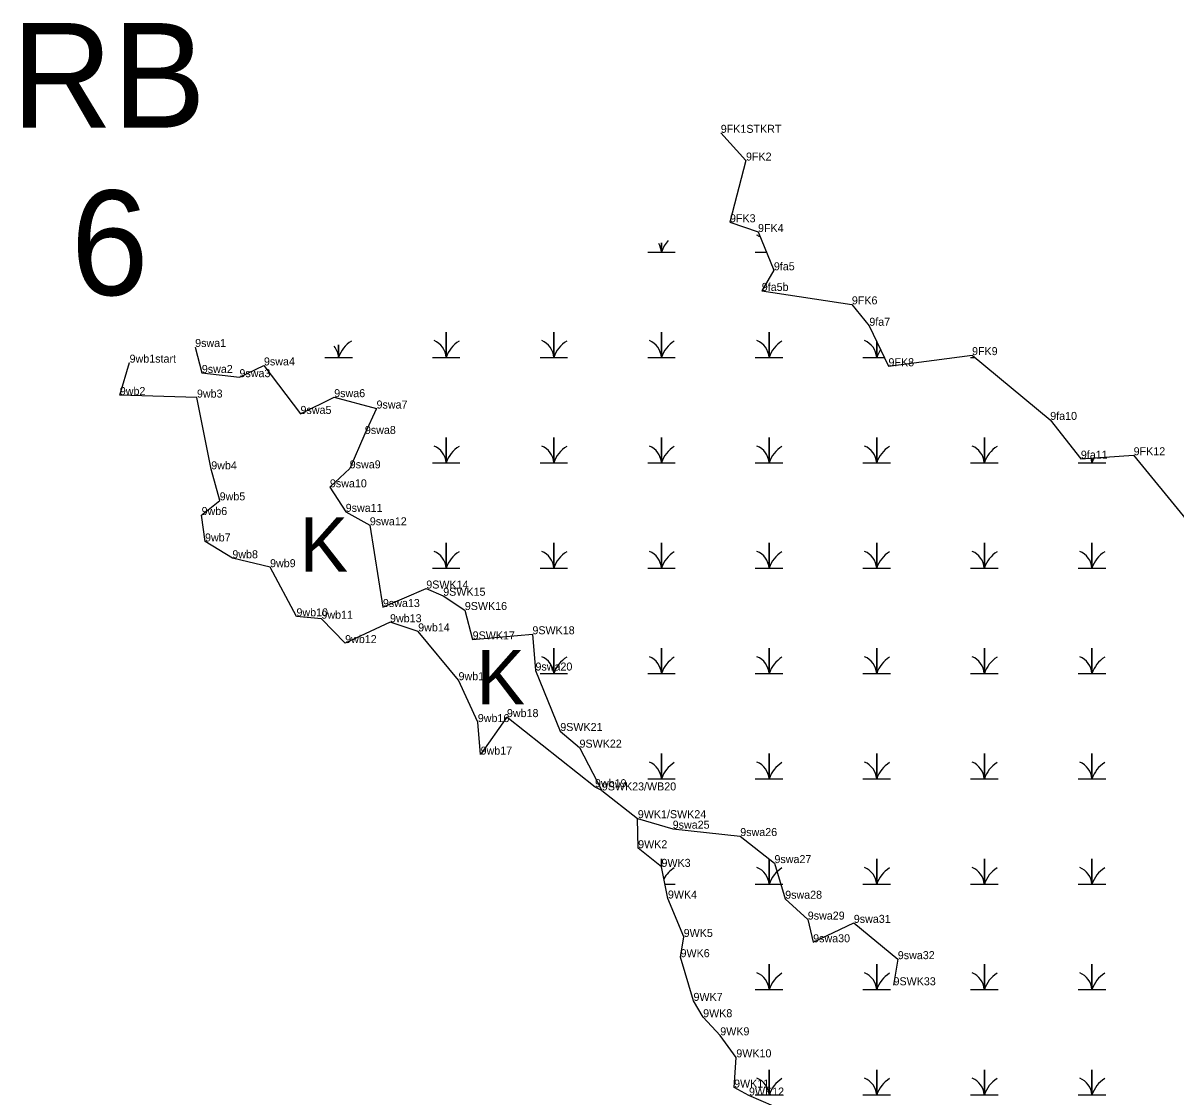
# Model space of a CAD drawing. Extents: x 2072529 to 2268796, y 436423 to 470406.
# Drawn here: x 2211830 to 2212551, y 449541 to 450212 of the extents above; entities that cross this region are included whole.
import ezdxf

# ---------------------------------------------------------------- set-up
doc = ezdxf.new("R2010")
doc.units = 0
for name, color, linetype in [('Default', 7, 'Continuous'), ('Exist Environmental Wetland Boundary', 7, 'Continuous'), ('Exist Environmental Wetland Boundary Cogo Comment', 7, 'Continuous'), ('Exist Hydro Jurisdictional Stream or Body of Water NEU Mitigable', 7, 'Continuous'), ('Exist Hydro Jurisdictional Stream or Body of Water NEU Mitigable Cogo Comment', 7, 'Continuous'), ('Exist Hydro Swamp or Marsh', 7, 'Continuous'), ('Old_Level_20', 7, 'Continuous')]:
    doc.layers.add(name, color=color, linetype=linetype)

msp = doc.modelspace()

# ---------------------------------------------------------------- linework, layer by layer
at = {"layer": 'Exist Environmental Wetland Boundary'}
for points in [[(2212266.45, 450143.23), (2212282.21, 450125.91), (2212272.2, 450087.37), (2212289.74, 450081.3), (2212299.63, 450057.38), (2212292.08, 450044.5), (2212348.37, 450036.11), (2212359.27, 450022.73), (2212371.25, 449997.47), (2212423.46, 450004.4), (2212472.32, 449963.94), (2212491.46, 449939.73), (2212524.45, 449941.86), (2212557.2, 449901.85)], [(2212192.12, 449732.56), (2212187.87, 449734.56), (2212132.83, 449778.34), (2212116.4, 449754.91), (2212114.63, 449775.24), (2212102.59, 449801.39), (2212077.37, 449831.86), (2212059.78, 449837.58), (2212031.73, 449824.56), (2212016.91, 449839.79), (2212001.31, 449841.26), (2211984.83, 449871.96), (2211961.26, 449877.54), (2211944.17, 449888.04), (2211942.04, 449904.54), (2211953.34, 449913.7), (2211948.07, 449933.08), (2211939.14, 449977.89), (2211890.93, 449979.47), (2211897.05, 449999.7)], [(2212299.43, 449535.26), (2212284.07, 449542), (2212274.77, 449546.95), (2212276.16, 449565.86), (2212266.13, 449579.6), (2212255.44, 449590.92), (2212249.41, 449601.12), (2212241.33, 449628.41), (2212243.27, 449641.04), (2212233.43, 449665.04), (2212229.4, 449684.82), (2212214.82, 449696.44), (2212214.5, 449715.1)]]:
    msp.add_lwpolyline(points, dxfattribs=at)
at = {"layer": 'Exist Hydro Jurisdictional Stream or Body of Water NEU Mitigable'}
msp.add_lwpolyline([(2211938, 450009.47), (2211942.18, 449993.25), (2211965.69, 449990.64), (2211981, 449997.97), (2212003.85, 449967.68), (2212024.9, 449978.15), (2212051.36, 449971.04), (2212044.07, 449955.16), (2212034.6, 449933.69), (2212022.23, 449921.84), (2212032.07, 449906.53), (2212047.16, 449898.13), (2212055.34, 449847.07), (2212082.43, 449858.63), (2212093.02, 449854.12), (2212106.52, 449845.21), (2212111.4, 449826.87), (2212148.76, 449830.07), (2212150.66, 449807.4), (2212166.16, 449769.66), (2212178.19, 449759.28), (2212192.12, 449732.56), (2212214.5, 449715.1), (2212236.4, 449708.65), (2212278.62, 449704.05), (2212299.99, 449687.16), (2212306.69, 449664.9), (2212320.81, 449651.88), (2212324.18, 449637.71), (2212349.58, 449649.84), (2212377.06, 449627.18), (2212374.41, 449610.86)], dxfattribs=at)
at = {"layer": 'Exist Hydro Swamp or Marsh'}
for points in [[(2212220.78, 450068.77), (2212229.39, 450068.77), (2212229.39, 450074.57)], [(2212229.39, 450074.57), (2212229.39, 450068.77), (2212237.99, 450068.77)], [(2212288.03, 450068.77), (2212294.92, 450068.77)], [(2212086.28, 450002.97), (2212094.89, 450002.97), (2212094.89, 450018.75), (2212094.89, 450002.97), (2212103.49, 450002.97)], [(2212153.53, 450002.97), (2212162.14, 450002.97), (2212162.14, 450018.75), (2212162.14, 450002.97), (2212170.74, 450002.97)], [(2212220.78, 450002.97), (2212229.39, 450002.97), (2212229.39, 450018.75), (2212229.39, 450002.97), (2212237.99, 450002.97)], [(2212288.03, 450002.97), (2212296.64, 450002.97), (2212296.64, 450018.75), (2212296.64, 450002.97), (2212305.24, 450002.97)], [(2212355.28, 450002.97), (2212363.89, 450002.97), (2212363.89, 450013)], [(2212363.89, 450013), (2212363.89, 450002.97), (2212368.64, 450002.97)], [(2212019.03, 450002.97), (2212027.64, 450002.97), (2212027.64, 450010.77)], [(2212027.64, 450010.77), (2212027.64, 450002.97), (2212036.24, 450002.97)], [(2212422.53, 450002.97), (2212425.18, 450002.97)], [(2212086.28, 449937.17), (2212094.89, 449937.17), (2212094.89, 449952.95), (2212094.89, 449937.17), (2212103.49, 449937.17)], [(2212153.53, 449937.17), (2212162.14, 449937.17), (2212162.14, 449952.95), (2212162.14, 449937.17), (2212170.74, 449937.17)], [(2212220.78, 449937.17), (2212229.39, 449937.17), (2212229.39, 449952.95), (2212229.39, 449937.17), (2212237.99, 449937.17)], [(2212288.03, 449937.17), (2212296.64, 449937.17), (2212296.64, 449952.95), (2212296.64, 449937.17), (2212305.24, 449937.17)], [(2212355.28, 449937.17), (2212363.89, 449937.17), (2212363.89, 449952.95), (2212363.89, 449937.17), (2212372.49, 449937.17)], [(2212422.53, 449937.17), (2212431.14, 449937.17), (2212431.14, 449952.95), (2212431.14, 449937.17), (2212439.74, 449937.17)], [(2212489.78, 449937.17), (2212498.39, 449937.17), (2212498.39, 449940.18)], [(2212498.39, 449940.18), (2212498.39, 449937.17), (2212506.99, 449937.17)], [(2212036.13, 449937.17), (2212036.24, 449937.17)], [(2212086.28, 449871.37), (2212094.89, 449871.37), (2212094.89, 449887.15), (2212094.89, 449871.37), (2212103.49, 449871.37)], [(2212153.53, 449871.37), (2212162.14, 449871.37), (2212162.14, 449887.15), (2212162.14, 449871.37), (2212170.74, 449871.37)], [(2212220.78, 449871.37), (2212229.39, 449871.37), (2212229.39, 449887.15), (2212229.39, 449871.37), (2212237.99, 449871.37)], [(2212288.03, 449871.37), (2212296.64, 449871.37), (2212296.64, 449887.15), (2212296.64, 449871.37), (2212305.24, 449871.37)], [(2212355.28, 449871.37), (2212363.89, 449871.37), (2212363.89, 449887.15), (2212363.89, 449871.37), (2212372.49, 449871.37)], [(2212422.53, 449871.37), (2212431.14, 449871.37), (2212431.14, 449887.15), (2212431.14, 449871.37), (2212439.74, 449871.37)], [(2212489.78, 449871.37), (2212498.39, 449871.37), (2212498.39, 449887.15), (2212498.39, 449871.37), (2212506.99, 449871.37)], [(2212153.53, 449805.57), (2212162.14, 449805.57), (2212162.14, 449821.35), (2212162.14, 449805.57), (2212170.74, 449805.57)], [(2212220.78, 449805.57), (2212229.39, 449805.57), (2212229.39, 449821.35), (2212229.39, 449805.57), (2212237.99, 449805.57)], [(2212288.03, 449805.57), (2212296.64, 449805.57), (2212296.64, 449821.35), (2212296.64, 449805.57), (2212305.24, 449805.57)], [(2212355.28, 449805.57), (2212363.89, 449805.57), (2212363.89, 449821.35), (2212363.89, 449805.57), (2212372.49, 449805.57)], [(2212422.53, 449805.57), (2212431.14, 449805.57), (2212431.14, 449821.35), (2212431.14, 449805.57), (2212439.74, 449805.57)], [(2212489.78, 449805.57), (2212498.39, 449805.57), (2212498.39, 449821.35), (2212498.39, 449805.57), (2212506.99, 449805.57)], [(2212220.78, 449739.77), (2212229.39, 449739.77), (2212229.39, 449755.55), (2212229.39, 449739.77), (2212237.99, 449739.77)], [(2212288.03, 449739.77), (2212296.64, 449739.77), (2212296.64, 449755.55), (2212296.64, 449739.77), (2212305.24, 449739.77)], [(2212355.28, 449739.77), (2212363.89, 449739.77), (2212363.89, 449755.55), (2212363.89, 449739.77), (2212372.49, 449739.77)], [(2212422.53, 449739.77), (2212431.14, 449739.77), (2212431.14, 449755.55), (2212431.14, 449739.77), (2212439.74, 449739.77)], [(2212489.78, 449739.77), (2212498.39, 449739.77), (2212498.39, 449755.55), (2212498.39, 449739.77), (2212506.99, 449739.77)], [(2212229.39, 449684.83), (2212229.39, 449689.75), (2212229.39, 449684.83)], [(2212288.03, 449673.97), (2212296.64, 449673.97), (2212296.64, 449689.75), (2212296.64, 449673.97), (2212305.24, 449673.97)], [(2212355.28, 449673.97), (2212363.89, 449673.97), (2212363.89, 449689.75), (2212363.89, 449673.97), (2212372.49, 449673.97)], [(2212422.53, 449673.97), (2212431.14, 449673.97), (2212431.14, 449689.75), (2212431.14, 449673.97), (2212439.74, 449673.97)], [(2212489.78, 449673.97), (2212498.39, 449673.97), (2212498.39, 449689.75), (2212498.39, 449673.97), (2212506.99, 449673.97)], [(2212231.61, 449673.97), (2212237.99, 449673.97)], [(2212288.03, 449608.17), (2212296.64, 449608.17), (2212296.64, 449623.95), (2212296.64, 449608.17), (2212305.24, 449608.17)], [(2212355.28, 449608.17), (2212363.89, 449608.17), (2212363.89, 449623.95), (2212363.89, 449608.17), (2212372.49, 449608.17)], [(2212422.53, 449608.17), (2212431.14, 449608.17), (2212431.14, 449623.95), (2212431.14, 449608.17), (2212439.74, 449608.17)], [(2212489.78, 449608.17), (2212498.39, 449608.17), (2212498.39, 449623.95), (2212498.39, 449608.17), (2212506.99, 449608.17)], [(2212288.03, 449542.37), (2212296.64, 449542.37), (2212296.64, 449558.15), (2212296.64, 449542.37), (2212305.24, 449542.37)], [(2212355.28, 449542.37), (2212363.89, 449542.37), (2212363.89, 449558.15), (2212363.89, 449542.37), (2212372.49, 449542.37)], [(2212422.53, 449542.37), (2212431.14, 449542.37), (2212431.14, 449558.15), (2212431.14, 449542.37), (2212439.74, 449542.37)], [(2212489.78, 449542.37), (2212498.39, 449542.37), (2212498.39, 449558.15), (2212498.39, 449542.37), (2212506.99, 449542.37)]]:
    msp.add_lwpolyline(points, dxfattribs=at)
for centre, radius, start, end in [((2212284.37, 450067.88), 12.3, 57.34248, 67.53497), ((2212217.12, 450067.88), 12.3, 4.14034, 30.12475), ((2212247.63, 450062.71), 19.22, 136.57429, 161.62219), ((2212045.88, 449996.91), 19.22, 122.12745, 161.62219), ((2212082.62, 450002.08), 12.3, 4.14034, 67.53497), ((2212113.13, 449996.91), 19.22, 122.12745, 161.62219), ((2212149.87, 450002.08), 12.3, 4.14034, 67.53497), ((2212180.38, 449996.91), 19.22, 122.12745, 161.62219), ((2212217.12, 450002.08), 12.3, 4.14034, 67.53497), ((2212247.63, 449996.91), 19.22, 122.12745, 161.62219), ((2212284.37, 450002.08), 12.3, 4.14034, 67.53497), ((2212314.88, 449996.91), 19.22, 122.12745, 161.62219), ((2212351.62, 450002.08), 12.3, 4.14034, 67.53497), ((2212015.37, 450002.08), 12.3, 4.14034, 39.4646), ((2212382.13, 449996.91), 19.22, 145.28894, 161.62219), ((2212082.62, 449936.28), 12.3, 4.14034, 67.53497), ((2212113.13, 449931.11), 19.22, 122.12745, 161.62219), ((2212149.87, 449936.28), 12.3, 4.14034, 67.53497), ((2212180.38, 449931.11), 19.22, 122.12745, 161.62219), ((2212217.12, 449936.28), 12.3, 4.14034, 67.53497), ((2212247.63, 449931.11), 19.22, 122.12745, 161.62219), ((2212284.37, 449936.28), 12.3, 4.14034, 67.53497), ((2212314.88, 449931.11), 19.22, 122.12745, 161.62219), ((2212351.62, 449936.28), 12.3, 4.14034, 67.53497), ((2212382.13, 449931.11), 19.22, 122.12745, 161.62219), ((2212418.87, 449936.28), 12.3, 4.14034, 67.53497), ((2212449.38, 449931.11), 19.22, 122.12745, 161.62219), ((2212486.12, 449936.28), 12.3, 4.14034, 18.30304), ((2212516.63, 449931.11), 19.22, 151.54291, 161.62219), ((2212082.62, 449870.48), 12.3, 4.14034, 67.53497), ((2212113.13, 449865.31), 19.22, 122.12745, 161.62219), ((2212149.87, 449870.48), 12.3, 4.14034, 67.53497), ((2212180.38, 449865.31), 19.22, 122.12745, 161.62219), ((2212217.12, 449870.48), 12.3, 4.14034, 67.53497), ((2212247.63, 449865.31), 19.22, 122.12745, 161.62219), ((2212284.37, 449870.48), 12.3, 4.14034, 67.53497), ((2212314.88, 449865.31), 19.22, 122.12745, 161.62219), ((2212351.62, 449870.48), 12.3, 4.14034, 67.53497), ((2212382.13, 449865.31), 19.22, 122.12745, 161.62219), ((2212418.87, 449870.48), 12.3, 4.14034, 67.53497), ((2212449.38, 449865.31), 19.22, 122.12745, 161.62219), ((2212486.12, 449870.48), 12.3, 4.14034, 67.53497), ((2212516.63, 449865.31), 19.22, 122.12745, 161.62219), ((2212149.87, 449804.68), 12.3, 4.14034, 67.53497), ((2212180.38, 449799.51), 19.22, 122.12745, 161.62219), ((2212217.12, 449804.68), 12.3, 4.14034, 67.53497), ((2212247.63, 449799.51), 19.22, 122.12745, 161.62219), ((2212284.37, 449804.68), 12.3, 4.14034, 67.53497), ((2212314.88, 449799.51), 19.22, 122.12745, 161.62219), ((2212351.62, 449804.68), 12.3, 4.14034, 67.53497), ((2212382.13, 449799.51), 19.22, 122.12745, 161.62219), ((2212418.87, 449804.68), 12.3, 4.14034, 67.53497), ((2212449.38, 449799.51), 19.22, 122.12745, 161.62219), ((2212486.12, 449804.68), 12.3, 4.14034, 67.53497), ((2212516.63, 449799.51), 19.22, 122.12745, 161.62219), ((2212217.12, 449738.88), 12.3, 4.14034, 67.53497), ((2212247.63, 449733.71), 19.22, 122.12745, 161.62219), ((2212284.37, 449738.88), 12.3, 4.14034, 67.53497), ((2212314.88, 449733.71), 19.22, 122.12745, 161.62219), ((2212351.62, 449738.88), 12.3, 4.14034, 67.53497), ((2212382.13, 449733.71), 19.22, 122.12745, 161.62219), ((2212418.87, 449738.88), 12.3, 4.14034, 67.53497), ((2212449.38, 449733.71), 19.22, 122.12745, 161.62219), ((2212486.12, 449738.88), 12.3, 4.14034, 67.53497), ((2212516.63, 449733.71), 19.22, 122.12745, 161.62219), ((2212247.63, 449667.91), 19.22, 122.12745, 150.42062), ((2212284.37, 449673.08), 12.3, 4.14034, 67.53497), ((2212314.88, 449667.91), 19.22, 122.12745, 161.62219), ((2212351.62, 449673.08), 12.3, 4.14034, 67.53497), ((2212382.13, 449667.91), 19.22, 122.12745, 161.62219), ((2212418.87, 449673.08), 12.3, 4.14034, 67.53497), ((2212449.38, 449667.91), 19.22, 122.12745, 161.62219), ((2212486.12, 449673.08), 12.3, 4.14034, 67.53497), ((2212516.63, 449667.91), 19.22, 122.12745, 161.62219), ((2212284.37, 449607.28), 12.3, 4.14034, 67.53497), ((2212314.88, 449602.11), 19.22, 122.12745, 161.62219), ((2212351.62, 449607.28), 12.3, 4.14034, 67.53497), ((2212382.13, 449602.11), 19.22, 122.12745, 161.62219), ((2212418.87, 449607.28), 12.3, 4.14034, 67.53497), ((2212449.38, 449602.11), 19.22, 122.12745, 161.62219), ((2212486.12, 449607.28), 12.3, 4.14034, 67.53497), ((2212516.63, 449602.11), 19.22, 122.12745, 161.62219), ((2212284.37, 449541.48), 12.3, 4.14034, 67.53497), ((2212314.88, 449536.31), 19.22, 122.12745, 161.62219), ((2212351.62, 449541.48), 12.3, 4.14034, 67.53497), ((2212382.13, 449536.31), 19.22, 122.12745, 161.62219), ((2212418.87, 449541.48), 12.3, 4.14034, 67.53497), ((2212449.38, 449536.31), 19.22, 122.12745, 161.62219), ((2212486.12, 449541.48), 12.3, 4.14034, 67.53497), ((2212516.63, 449536.31), 19.22, 122.12745, 161.62219)]:
    msp.add_arc(centre, radius, start, end, dxfattribs=at)
at = {"layer": 'Old_Level_20'}
for p, q in [((2212266.45, 450143.23), (2212266.45, 450143.23)), ((2212282.21, 450125.91), (2212282.21, 450125.91)), ((2212272.2, 450087.37), (2212272.2, 450087.37)), ((2212289.74, 450081.3), (2212289.74, 450081.3)), ((2212299.63, 450057.38), (2212299.63, 450057.38)), ((2212299.63, 450057.38), (2212299.63, 450057.38)), ((2212292.08, 450044.5), (2212292.08, 450044.5)), ((2212292.08, 450044.5), (2212292.08, 450044.5)), ((2212348.37, 450036.11), (2212348.37, 450036.11)), ((2212359.27, 450022.73), (2212359.27, 450022.73)), ((2212359.27, 450022.73), (2212359.27, 450022.73)), ((2211938, 450009.47), (2211938, 450009.47)), ((2211897.05, 449999.7), (2211897.05, 449999.7)), ((2211981, 449997.97), (2211981, 449997.97)), ((2212423.46, 450004.4), (2212423.46, 450004.4)), ((2211942.18, 449993.25), (2211942.18, 449993.25)), ((2211965.69, 449990.64), (2211965.69, 449990.64)), ((2212371.25, 449997.47), (2212371.25, 449997.47)), ((2211890.93, 449979.47), (2211890.93, 449979.47)), ((2211939.14, 449977.89), (2211939.14, 449977.89)), ((2212024.9, 449978.15), (2212024.9, 449978.15)), ((2212051.36, 449971.04), (2212051.36, 449971.04)), ((2212003.85, 449967.68), (2212003.85, 449967.68)), ((2212472.32, 449963.94), (2212472.32, 449963.94)), ((2212472.32, 449963.94), (2212472.32, 449963.94)), ((2212044.07, 449955.16), (2212044.07, 449955.16)), ((2212524.45, 449941.86), (2212524.45, 449941.86)), ((2211948.07, 449933.08), (2211948.07, 449933.08)), ((2212034.6, 449933.69), (2212034.6, 449933.69)), ((2212491.46, 449939.73), (2212491.46, 449939.73)), ((2212491.46, 449939.73), (2212491.46, 449939.73)), ((2212022.23, 449921.84), (2212022.23, 449921.84)), ((2211953.34, 449913.7), (2211953.34, 449913.7)), ((2211942.04, 449904.54), (2211942.04, 449904.54)), ((2212032.07, 449906.53), (2212032.07, 449906.53)), ((2212047.16, 449898.13), (2212047.16, 449898.13)), ((2211944.17, 449888.04), (2211944.17, 449888.04)), ((2211961.26, 449877.54), (2211961.26, 449877.54)), ((2211984.83, 449871.96), (2211984.83, 449871.96)), ((2212082.43, 449858.63), (2212082.43, 449858.63)), ((2212093.02, 449854.12), (2212093.02, 449854.12)), ((2212055.34, 449847.07), (2212055.34, 449847.07)), ((2212001.31, 449841.26), (2212001.31, 449841.26)), ((2212016.91, 449839.79), (2212016.91, 449839.79)), ((2212106.52, 449845.21), (2212106.52, 449845.21)), ((2212059.78, 449837.58), (2212059.78, 449837.58)), ((2212077.37, 449831.86), (2212077.37, 449831.86)), ((2212111.4, 449826.87), (2212111.4, 449826.87)), ((2212148.76, 449830.07), (2212148.76, 449830.07)), ((2212031.73, 449824.56), (2212031.73, 449824.56)), ((2212150.66, 449807.4), (2212150.66, 449807.4)), ((2212102.59, 449801.39), (2212102.59, 449801.39)), ((2212114.63, 449775.24), (2212114.63, 449775.24)), ((2212132.83, 449778.34), (2212132.83, 449778.34)), ((2212166.16, 449769.66), (2212166.16, 449769.66)), ((2212116.4, 449754.91), (2212116.4, 449754.91)), ((2212178.19, 449759.28), (2212178.19, 449759.28)), ((2212187.85, 449734.53), (2212187.85, 449734.53)), ((2212192.12, 449732.56), (2212192.12, 449732.56)), ((2212192.12, 449732.56), (2212192.12, 449732.56)), ((2212214.5, 449715.1), (2212214.5, 449715.1)), ((2212214.5, 449715.1), (2212214.5, 449715.1)), ((2212236.4, 449708.65), (2212236.4, 449708.65)), ((2212278.62, 449704.05), (2212278.62, 449704.05)), ((2212214.82, 449696.44), (2212214.82, 449696.44)), ((2212229.4, 449684.82), (2212229.4, 449684.82)), ((2212299.99, 449687.16), (2212299.99, 449687.16)), ((2212233.43, 449665.04), (2212233.43, 449665.04)), ((2212306.69, 449664.9), (2212306.69, 449664.9)), ((2212320.81, 449651.88), (2212320.81, 449651.88)), ((2212349.58, 449649.84), (2212349.58, 449649.84)), ((2212243.27, 449641.04), (2212243.27, 449641.04)), ((2212324.18, 449637.71), (2212324.18, 449637.71)), ((2212241.33, 449628.41), (2212241.33, 449628.41)), ((2212377.06, 449627.18), (2212377.06, 449627.18)), ((2212374.41, 449610.86), (2212374.41, 449610.86)), ((2212249.41, 449601.12), (2212249.41, 449601.12)), ((2212255.44, 449590.92), (2212255.44, 449590.92)), ((2212266.13, 449579.6), (2212266.13, 449579.6)), ((2212276.16, 449565.86), (2212276.16, 449565.86)), ((2212274.77, 449546.95), (2212274.77, 449546.95)), ((2212284.07, 449542), (2212284.07, 449542))]:
    msp.add_line(p, q, dxfattribs=at)

# ---------------------------------------------------------------- texts
at = {"layer": 'Default'}
for s, p in [('RB', (2211823.3, 450146.43)), ('6', (2211860.32, 450041.89))]:
    msp.add_text(s, height=65.34, dxfattribs=at).set_placement(p)
at = {"layer": 'Exist Environmental Wetland Boundary Cogo Comment'}
for s, p in [('9FK1STKRT', (2212266.45, 450143.23)), ('9FK2', (2212282.21, 450125.91)), ('9FK3', (2212272.2, 450087.37)), ('9FK4', (2212289.74, 450081.3)), ('9fa5', (2212299.63, 450057.38)), ('9fa5b', (2212292.08, 450044.5)), ('9FK6', (2212348.37, 450036.11)), ('9fa7', (2212359.27, 450022.73)), ('9wb1start', (2211897.05, 449999.7)), ('9FK9', (2212423.46, 450004.4)), ('9FK8', (2212371.25, 449997.47)), ('9wb2', (2211890.93, 449979.47)), ('9wb3', (2211939.14, 449977.89)), ('9fa10', (2212472.32, 449963.94)), ('9fa11', (2212491.46, 449939.73)), ('9FK12', (2212524.45, 449941.86)), ('9wb4', (2211948.07, 449933.08)), ('9wb5', (2211953.34, 449913.7)), ('9wb6', (2211942.04, 449904.54)), ('9wb7', (2211944.17, 449888.04)), ('9wb8', (2211961.26, 449877.54)), ('9wb9', (2211984.83, 449871.96)), ('9wb10', (2212001.31, 449841.26)), ('9wb11', (2212016.91, 449839.79)), ('9wb13', (2212059.78, 449837.58)), ('9wb14', (2212077.37, 449831.86)), ('9wb12', (2212031.73, 449824.56)), ('9wb15', (2212102.59, 449801.39)), ('9wb18', (2212132.83, 449778.34)), ('9wb16', (2212114.63, 449775.24)), ('9wb17', (2212116.4, 449754.91)), ('9WK2', (2212214.82, 449696.44)), ('9WK3', (2212229.4, 449684.82)), ('9WK4', (2212233.43, 449665.04)), ('9WK5', (2212243.27, 449641.04)), ('9WK6', (2212241.33, 449628.41)), ('9WK7', (2212249.41, 449601.12)), ('9WK8', (2212255.44, 449590.92)), ('9WK9', (2212266.13, 449579.6)), ('9WK10', (2212276.16, 449565.86)), ('9WK11', (2212274.77, 449546.95)), ('9WK12', (2212284.07, 449542))]:
    msp.add_text(s, height=5, dxfattribs=at).set_placement(p)
at = {"layer": 'Exist Hydro Jurisdictional Stream or Body of Water NEU Mitigable Cogo Comment'}
for s, p in [('9swa1', (2211938, 450009.47)), ('9swa2', (2211942.18, 449993.25)), ('9swa4', (2211981, 449997.97)), ('9swa3', (2211965.69, 449990.64)), ('9swa6', (2212024.9, 449978.15)), ('9swa7', (2212051.36, 449971.04)), ('9swa5', (2212003.85, 449967.68)), ('9swa8', (2212044.07, 449955.16)), ('9swa9', (2212034.6, 449933.69)), ('9swa10', (2212022.23, 449921.84)), ('9swa11', (2212032.07, 449906.53)), ('9swa12', (2212047.16, 449898.13)), ('9SWK14', (2212082.43, 449858.63)), ('9SWK15', (2212093.02, 449854.12)), ('9swa13', (2212055.34, 449847.07)), ('9SWK16', (2212106.52, 449845.21)), ('9SWK17', (2212111.4, 449826.87)), ('9SWK18', (2212148.76, 449830.07)), ('9swa20', (2212150.66, 449807.4)), ('9SWK21', (2212166.16, 449769.66)), ('9SWK22', (2212178.19, 449759.28)), ('9wb19', (2212187.87, 449734.56)), ('9SWK23/WB20', (2212192.12, 449732.56)), ('9WK1/SWK24', (2212214.62, 449715.21)), ('9swa25', (2212236.4, 449708.65)), ('9swa26', (2212278.62, 449704.05)), ('9swa27', (2212299.99, 449687.16)), ('9swa28', (2212306.69, 449664.9)), ('9swa29', (2212320.81, 449651.88)), ('9swa31', (2212349.58, 449649.84)), ('9swa30', (2212324.18, 449637.71)), ('9swa32', (2212377.06, 449627.18)), ('9SWK33', (2212374.41, 449610.86))]:
    msp.add_text(s, height=5, dxfattribs=at).set_placement(p)
at = {"layer": 'Exist Hydro Swamp or Marsh'}
for p in [(2212003.3, 449869.08), (2212113.78, 449786.35)]:
    msp.add_text('K', height=34, dxfattribs=at).set_placement(p)

doc.saveas('drawing.dxf')
